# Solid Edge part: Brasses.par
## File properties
Author: CADCIM
Template: iso part.par
Last saved by: CADCIM
Revision: 11
Application: Solid Edge
Accuracy: 0.990
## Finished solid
Body 1: solid body, 16 faces, 18 edges, 0 vertices.
  Faces by surface: cylinder 9, plane 7
  Edges by curve: circle 14, intersection 4
Bounding box of the edges (mm): 78.000 x 64.000 x 64.000, from (-39, -32, -32) to (39, 32, 32).
Cylindrical faces by radius (mm): R3 x2, R4 x1, R16 x1, R22 x1, R24 x2, R32 x2
Planar faces by outward normal: +x 3, +z 1, -x 3
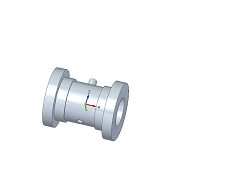
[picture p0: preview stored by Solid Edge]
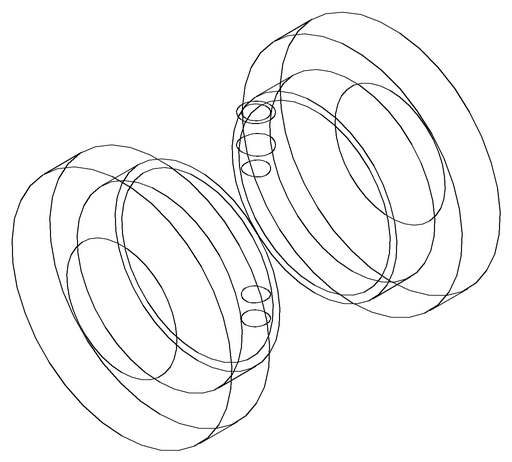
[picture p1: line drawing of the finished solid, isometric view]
